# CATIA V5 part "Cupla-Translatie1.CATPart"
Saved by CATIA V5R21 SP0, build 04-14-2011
Part number: Cupla T1
Bounding box of the stored display mesh (mm): x -75 to 75, y -75 to 75, z 0 to 700
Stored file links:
  C:\Users\MIRCEA\Desktop\PRRO\CATIAV5\Cupla-Translatie1.CATPart
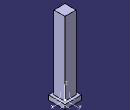
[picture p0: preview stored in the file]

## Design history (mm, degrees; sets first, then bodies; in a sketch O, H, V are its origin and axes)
AxisSystem1: origin (0, 0, 0), X (1, 0, 0), Y (0, 1, 0), Z (0, 0, 1)
Body1 (main body)
  Sketch1 on xy-plane, origin (0, 0, 0), H (1, 0, 0), V (0, 1, 0)
    line L1 (50, 50) -> (50, -50)
    line L2 (50, -50) -> (-50, -50)
    line L3 (-50, -50) -> (-50, 50)
    line L4 (-50, 50) -> (50, 50)
    point P2 (50, -50)
    distance L1 L3 = 100
    distance P2 H = 50
    vertical: L1 V, L3 V
    horizontal: L2 H, L4 H
    equidistance: L1 L3 O, L2 L4 O
  Pad1: profile Sketch1, direction (0, 0, 1), length 700
  Sketch2 on xy-plane, origin (0, 0, 0), H (1, 0, 0), V (0, 1, 0)
    line L1 (75, 75) -> (75, -75)
    line L2 (75, -75) -> (-75, -75)
    line L3 (-75, -75) -> (-75, 75)
    line L4 (-75, 75) -> (75, 75)
    distance L2 L4 = 150
    distance L1 L3 = 150
    vertical: L1 V, L3 V
    horizontal: L2 H, L4 H
    equidistance: L1 L3 O, L2 L4 O
  Pad2: profile Sketch2, direction (0, 0, 1), length 40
